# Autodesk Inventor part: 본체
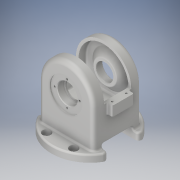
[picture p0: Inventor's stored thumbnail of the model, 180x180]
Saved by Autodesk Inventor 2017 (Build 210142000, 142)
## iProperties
Part Number: 본체
Material: 알루미늄 6061
Document SubType Name: Modeling
Designer: MRC
Density: 2.7 g/cm^3
Appearance: 알루미늄 - 평지
Mass: 1199.23 g
Surface Area: 1051.82 cm^2
Volume: 444.159 cm^3
Author: MRC
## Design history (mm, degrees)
sketch "스케치1"
  geometry: C1 r 71 at (0, 0); 1 further point
  constraints: 1 centre point, 1 coincident
  dimensions: "d0" = 142 diameter of C1
extrude "돌출1" new body sketch "스케치1" distance "d1" = 13; taper "d2" = 0 deg
sketch "스케치2"
  geometry: L1 (-71, 0)-(71, 0) reference; L2 (51, 81)-(51, 0); L3 (51, 0)-(-51, 0); L4 (-51, 0)-(-51, 81); A1 r 51 centre (0, 81) between (51, 81) and (-51, 81); 2 further points
  constraints: 6 end point, 2 point on circle, 2 tangent, 1 centre point, 1 midpoint, 1 parallel, 1 point on line, 1 vertical alignment
  dimensions: "d3" = 102 diameter of A1; "d4" = 81 distance of point (0, 0) A1.centre; "d5" = 102 distance of L2.end L3.end; "d6" = 81 distance of L3.end L4.end
extrude "돌출2" join sketch "스케치2" stored distance "d7" = 88; taper "d8" = 0 deg
sketch "스케치3"
  geometry: L1 (81, 20)-(61, 20); L2 (61, 20)-(61, -20); L3 (61, -20)-(81, -20); L4 (81, -20)-(81, 20); 2 further points
  constraints: 8 end point, 2 parallel, 1 horizontal, 1 horizontal alignment, 1 midpoint, 1 perpendicular
  dimensions: "d9" = 20 distance of L3.end L2.end; "d10" = 40 distance of L2.end L1.end; "d11" = 81 distance from line of point (0, 0) L4
extrude "돌출3" join sketch "스케치3" stored distance "d12" = 122; taper "d13" = 0 deg
sketch "스케치4"
  geometry: L1 (46, 81)-(46, 40); L2 (46, 40)-(-46, 40); L3 (-46, 40)-(-46, 81); A1 r 51 centre (0, 81) between (51, 81) and (-51, 81) reference; A2 r 46 centre (0, 81) between (46, 81) and (-46, 81); 1 further point
  constraints: 6 end point, 2 point on circle, 1 centre point, 1 parallel, 1 perpendicular, 1 tangent
  dimensions: "d14" = 40 distance from line of L2 point (0, 0); "d15" = 5 radial gap between concentric circles of A1 A2; "d16" = 92 distance of L1.end L2.end; "d17" = 41 distance of L1.start L1.end
extrude "돌출4" cut sketch "스케치4" stored distance "d18" = 78; taper "d19" = 0 deg
sketch "스케치5"
  geometry: L1 (127, 39)-(81, 39) reference; L2 (81, 39)-(40, 39) reference; L3 (114.5, 39)-(102.5, 27); L4 (102.5, 27)-(81, 27); L5 (81, 27)-(81, 39); L6 (81, 39)-(114.5, 39); 1 further point
  constraints: 8 end point, 1 collinear, 1 horizontal, 1 point on line
  dimensions: "d20" = 135 deg angle of L4 L3; "d22" = 67 diameter of L3.start L5; "d23" = 12 distance of L4.end L1.end; "d25" = 81 horizontal distance of point (0, 0) L4.end
revolve "회전1" sketch "스케치5" stored, may be unused: angle "d26" = 90 deg
sketch "스케치6"
  geometry: L1 (81, -39)-(81, 39) reference; L2 (154.956, 25)-(81, 25); L3 (81, 25)-(81, -25); L4 (81, -25)-(154.956, -25); L5 (154.956, -25)-(154.956, 25); 2 further points
  constraints: 8 end point, 2 parallel, 1 horizontal, 1 horizontal alignment, 1 midpoint, 1 perpendicular, 1 point on line
  dimensions: "d27" = 50 distance of L4.end L2.start; "d28" = 73.9558 distance of L2.start L2.end
extrude "돌출5" cut sketch "스케치6" stored distance "d29" = 78; taper "d30" = 0 deg
sketch "스케치7"
  geometry: C1 r 16 at (0, 81); A1 r 51 centre (0, 81) between (51, 81) and (-51, 81) reference; 1 further point
  constraints: 1 centre point, 1 coincident
  dimensions: "d31" = 32 diameter of C1
extrude "돌출6" cut sketch "스케치7" stored distance "d32" = 78; taper "d33" = 0 deg
sketch "스케치8"
  geometry: C1 r 16 at (0, 81) reference; C2 r 30 at (0, 81); 1 further point
  constraints: 1 centre point, 1 coincident
  dimensions: "d34" = 60 diameter of C2
extrude "돌출7" cut sketch "스케치8" distance "d35" = 2; taper "d36" = 0 deg
sketch "스케치9"
  geometry: C1 r 30 at (0, 0) reference; C2 r 18.5 at (0, 0); 1 further point
  constraints: 1 centre point, 1 coincident
  dimensions: "d37" = 37 diameter of C2
extrude "돌출8" cut sketch "스케치9" distance "d38" = 13; taper "d39" = 0 deg
sketch "스케치10"
  geometry: L1 (19, -28)-(-12.839, -28); L2 (-12.839, -28)-(-12.839, 28); L3 (-12.839, 28)-(19, 28); L4 (19, 28)-(19, -28); 2 further points
  constraints: 8 end point, 2 parallel, 1 horizontal, 1 horizontal alignment, 1 midpoint, 1 perpendicular
  dimensions: "d40" = 19 distance from line of L4 point (0, 0); "d41" = 56 distance of L1.end L2.end; "d42" = 31.83878 distance of L2.end L3.end
extrude "돌출9" cut sketch "스케치10" stored distance "d43" = 13; taper "d44" = 0 deg
sketch "스케치11"
  geometry: C1 r 30 at (0, 0); 1 further point
  constraints: 1 centre point, 1 coincident
  dimensions: "d45" = 60 diameter of C1
extrude "돌출10" cut sketch "스케치11" distance "d46" = 22; taper "d47" = 0 deg
sketch "스케치12"
  geometry: C1 r 14 at (0, 0); 1 further point
  constraints: 1 centre point, 1 coincident
  dimensions: "d48" = 28 diameter of C1
extrude "돌출11" cut sketch "스케치12" distance "d49" = 15; taper "d50" = 0 deg
sketch "스케치13"
  geometry: C1 r 11 at (0, 0); 1 further point
  constraints: 1 centre point, 1 coincident
  dimensions: "d51" = 22 diameter of C1
extrude "돌출12" cut sketch "스케치13" distance "d52" = 15; taper "d53" = 0 deg
sketch "스케치14"
  geometry: L1 (-25, 55)-(25, 55); L2 (25, 55)-(25, -55); L3 (25, -55)-(-25, -55); L4 (-25, -55)-(-25, 55); L5 (-25, 55)-(25, -55); L6 (25, 55)-(-25, -55); 5 further points
  constraints: 12 end point, 4 coincident, 2 midpoint, 2 parallel, 1 horizontal, 1 perpendicular
  dimensions: "d54" = 50 distance of L2.end L3.end; "d55" = 110 distance of L1.end L2.end
hole "구멍1" sketch "스케치14" at (25, 55), (25, -55), (-25, -55), (-25, 55) diameter "d56" = 9; stored, may be unused: countersink angle "d60" = 90 deg, drill point angle "d62" = 118 deg; dims "d57" = 6, "d58" = 15, "d59" = 8.8, "d61" = 8
sketch "스케치15"
  geometry: C1 r 30 at (0, 0) reference; A1 r 23 centre (0, 0) between (0, 23) and (23, 0); 3 further points
  constraints: 4 point on circle, 2 horizontal alignment, 2 vertical alignment, 1 centre point, 1 coincident
  dimensions: "d63" = 46 diameter of A1
hole "구멍2" sketch "스케치15" at (0, 23), (23, 0), (-23, 0), (0, -23) diameter "d64" = 3.242; stored, may be unused: countersink angle "d68" = 90 deg, drill point angle "d70" = 118 deg; dims "d65" = 8, "d66" = 15, "d67" = 8.8, "d69" = 10
sketch "스케치16"
  geometry: L1 (3, 33)-(-105, 33); L2 (-105, 33)-(-105, 7); L3 (-105, 7)-(3, 7); L4 (3, 7)-(3, 33); L5 (3, 33)-(-105, 7); L6 (-105, 33)-(3, 7); 5 further points
  constraints: 12 end point, 4 coincident, 2 midpoint, 2 parallel, 1 horizontal, 1 perpendicular
  dimensions: "d71" = 108 distance of L3.end L2.end; "d72" = 26 distance of L2.end L1.end
hole "구멍3" sketch "스케치16" at (3, 7), (3, 33), (-105, 33), (-105, 7) diameter "d73" = 3.242; stored, may be unused: countersink angle "d77" = 90 deg, drill point angle "d79" = 118 deg; dims "d74" = 8, "d75" = 15, "d76" = 8.8, "d78" = 10
sketch "스케치17"
  geometry: A1 r 23 centre (0, 0) between (0, -23) and (-23, 0); 3 further points
  constraints: 4 point on circle, 2 horizontal alignment, 2 vertical alignment, 1 centre point, 1 coincident
  dimensions: "d80" = 46 diameter of A1
hole "구멍4" sketch "스케치17" at (0, -23), (-23, 0), (23, 0), (0, 23) diameter "d81" = 3.242; stored, may be unused: countersink angle "d85" = 90 deg, drill point angle "d87" = 118 deg; dims "d82" = 8, "d83" = 15, "d84" = 8.8, "d86" = 10
sketch "스케치18"
  geometry: L1 (65.246, 0)-(65.246, 13) reference; L2 (-65.246, 13)-(65.246, 13) reference; L3 (-65.246, 13)-(-65.246, 0) reference; L4 (65.246, 0)-(-65.246, 0) reference; 3 further points
  constraints: 1 midpoint, 1 vertical alignment, 1 other
  dimensions: "d88" = 30 vertical distance of point (0, 30) L1.start
feature "엠보싱1" sketch "스케치18" dims "d0" = 142, "d89" = 0.5, "d90" = 0
fillet "모깎기1" dims "d91" = 6
fillet "모깎기2" dims "d92" = 8
fillet "모깎기3" dims "d93" = 0.3
fillet "모깎기4" dims "d94" = 3
fillet "모깎기5" dims "d95" = 3
fillet "모깎기6" dims "d96" = 3
fillet "모깎기7" dims "d97" = 3
fillet "모깎기8" dims "d98" = 3
fillet "모깎기9" dims "d99" = 3
fillet "모깎기10" dims "d100" = 3
fillet "모깎기11" dims "d101" = 3
chamfer "모따기1" distance "d102" = 1; stored, may be unused: second distance "d103" = 2, angle "d104" = 45 deg
node "솔리드1"
mirror "미러1"
mirror "미러2"
mirror "미러3"
node "투영된 루프1"
